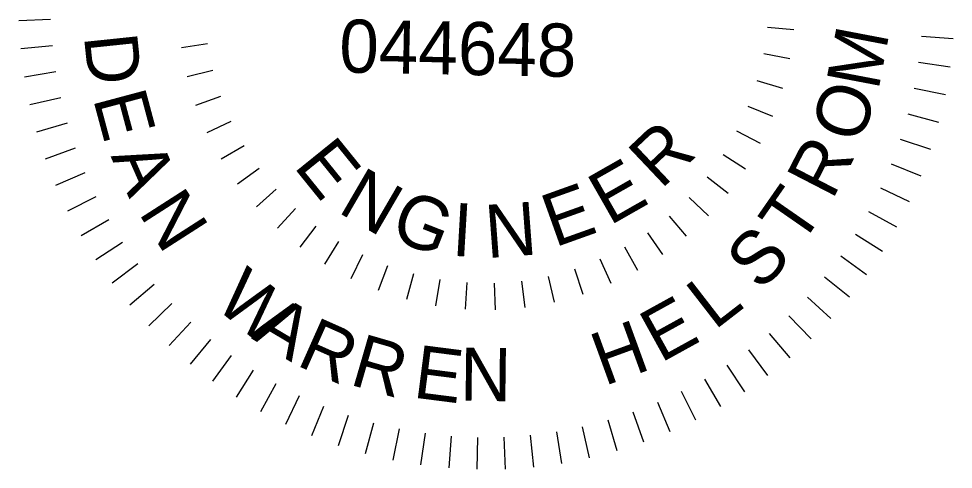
# Model space of a CAD drawing. Extents: x 0 to 4772457, y -312190 to 1506.
# Drawn here: x 3.6903 to 3.8118, y 1.3954 to 1.454 of the extents above; entities that cross this region are included whole.
import ezdxf

# ---------------------------------------------------------------- set-up
doc = ezdxf.new("R2010")
doc.units = 0
doc.layers.add('Phasing Diagram CELL', color=7, linetype='Continuous')

msp = doc.modelspace()

# ---------------------------------------------------------------- linework, layer by layer
at = {"layer": 'Phasing Diagram CELL'}
for p, q in [((3.6903447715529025, 1.4537591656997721), (3.6944888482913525, 1.4539254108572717)), ((3.7911069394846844, 1.452534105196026), (3.787667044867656, 1.4528508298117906)), ((3.7114942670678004, 1.450262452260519), (3.714908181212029, 1.4507772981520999)), ((3.8118311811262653, 1.451351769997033), (3.8076969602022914, 1.4516822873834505)), ((3.690606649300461, 1.4500932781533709), (3.6947298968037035, 1.4505087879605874)), ((3.787188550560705, 1.4494652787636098), (3.7905882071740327, 1.44882345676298)), ((3.811424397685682, 1.4476989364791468), (3.807320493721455, 1.448277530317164)), ((3.6910828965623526, 1.446448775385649), (3.695176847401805, 1.447113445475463)), ((3.7122503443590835, 1.4464578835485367), (3.7156017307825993, 1.4473003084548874)), ((3.7896535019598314, 1.4449241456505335), (3.7863377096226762, 1.4458985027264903)), ((3.8108040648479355, 1.4440764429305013), (3.8067396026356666, 1.444902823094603)), ((3.69178348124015, 1.442842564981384), (3.6958304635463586, 1.443748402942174)), ((3.7133774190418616, 1.44274915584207), (3.7166323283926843, 1.4439105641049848)), ((3.788380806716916, 1.4412629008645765), (3.78517456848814, 1.442552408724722)), ((3.809961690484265, 1.4405008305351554), (3.8059533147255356, 1.4415660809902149)), ((3.692698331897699, 1.4392751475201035), (3.6966905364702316, 1.4404305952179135)), ((3.7148582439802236, 1.4391704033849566), (3.71798235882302, 1.4406427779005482)), ((3.7867591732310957, 1.4377457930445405), (3.7836958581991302, 1.439340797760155)), ((3.716667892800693, 1.4357480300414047), (3.7196432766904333, 1.4375065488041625)), ((3.808905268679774, 1.4369723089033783), (3.80496210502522, 1.438285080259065)), ((3.6938293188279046, 1.4357806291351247), (3.697740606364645, 1.4371775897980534)), ((3.784815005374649, 1.4343977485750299), (3.7819120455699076, 1.436272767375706)), ((3.8076367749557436, 1.4335254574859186), (3.8037843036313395, 1.4350763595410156)), ((3.695176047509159, 1.4323583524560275), (3.6989889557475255, 1.4339808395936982)), ((3.7188069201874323, 1.4325079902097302), (3.7215991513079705, 1.4345531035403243)), ((3.782549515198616, 1.431244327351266), (3.7798405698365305, 1.4333988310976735)), ((3.721250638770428, 1.4295012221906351), (3.7238255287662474, 1.4317997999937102)), ((3.8061558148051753, 1.4301596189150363), (3.802409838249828, 1.4319314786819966)), ((3.6967131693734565, 1.4290194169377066), (3.700427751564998, 1.430874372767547)), ((3.77998826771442, 1.42833796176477), (3.777507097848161, 1.4307361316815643)), ((3.7239649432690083, 1.426738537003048), (3.7263132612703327, 1.4292814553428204)), ((3.804487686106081, 1.4268835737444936), (3.8008495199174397, 1.4288845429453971)), ((3.6984578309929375, 1.4257783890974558), (3.7020483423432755, 1.427858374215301)), ((3.777166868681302, 1.425684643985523), (3.7749211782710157, 1.4283175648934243)), ((3.72694218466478, 1.4242536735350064), (3.7290285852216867, 1.4270070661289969)), ((3.774093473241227, 1.4233188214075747), (3.7721178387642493, 1.4261532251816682)), ((3.802616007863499, 1.423714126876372), (3.799110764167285, 1.4259353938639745)), ((3.700393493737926, 1.4226535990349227), (3.703851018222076, 1.4249419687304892)), ((3.7301398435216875, 1.4220642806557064), (3.7319554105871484, 1.4250115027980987)), ((3.7708117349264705, 1.4212581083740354), (3.769114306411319, 1.4242747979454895)), ((3.7335405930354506, 1.4201963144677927), (3.7350593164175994, 1.423304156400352)), ((3.767339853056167, 1.4195262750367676), (3.765945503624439, 1.422691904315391)), ((3.800558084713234, 1.4206687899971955), (3.7971935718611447, 1.4230929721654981)), ((3.7025114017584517, 1.4196536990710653), (3.705827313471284, 1.4221429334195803)), ((3.73710193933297, 1.4186597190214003), (3.7383152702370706, 1.4219020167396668)), ((3.76371977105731, 1.418132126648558), (3.7626360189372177, 1.4214201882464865)), ((3.7416631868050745, 1.4208241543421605), (3.7407650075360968, 1.4174812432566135)), ((3.7599874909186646, 1.4171001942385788), (3.759223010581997, 1.420475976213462)), ((3.7983223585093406, 1.4177553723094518), (3.795108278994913, 1.4203736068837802)), ((3.7048126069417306, 1.416778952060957), (3.707969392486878, 1.4194684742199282)), ((3.744581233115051, 1.4166598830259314), (3.745145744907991, 1.4200692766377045)), ((3.748430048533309, 1.416206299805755), (3.748660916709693, 1.4196565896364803)), ((3.752303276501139, 1.4161295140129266), (3.752209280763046, 1.4195864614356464)), ((3.7561675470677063, 1.4164302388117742), (3.7557382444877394, 1.4198591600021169)), ((3.7959100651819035, 1.4149738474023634), (3.7928621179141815, 1.417786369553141)), ((3.7072785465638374, 1.4140553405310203), (3.7102679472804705, 1.4169281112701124)), ((3.7933373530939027, 1.4123499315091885), (3.790464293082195, 1.4153391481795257)), ((3.709902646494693, 1.4114823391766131), (3.7127150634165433, 1.414529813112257)), ((3.790614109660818, 1.4098834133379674), (3.78792411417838, 1.4130403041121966)), ((3.712684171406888, 1.4090700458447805), (3.715302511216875, 1.4122845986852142)), ((3.7877389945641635, 1.4075827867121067), (3.7852494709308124, 1.410898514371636)), ((3.7155976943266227, 1.4068347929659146), (3.71802177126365, 1.4101988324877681)), ((3.7186427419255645, 1.4047766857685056), (3.720864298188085, 1.408282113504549)), ((3.7847388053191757, 1.4054646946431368), (3.782450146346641, 1.4089220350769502)), ((3.781614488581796, 1.4035289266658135), (3.7795337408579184, 1.4071193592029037)), ((3.721812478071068, 1.4029051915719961), (3.723813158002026, 1.406543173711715)), ((3.725088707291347, 1.4012367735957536), (3.726860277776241, 1.404982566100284)), ((3.778373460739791, 1.4017842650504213), (3.776518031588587, 1.4054989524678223)), ((3.7284542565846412, 1.3997556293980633), (3.730005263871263, 1.4036085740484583)), ((3.775033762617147, 1.4002470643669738), (3.77341203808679, 1.4040600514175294)), ((3.731901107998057, 1.398487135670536), (3.7332141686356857, 1.4024304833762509)), ((3.7716117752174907, 1.3989005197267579), (3.7702148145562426, 1.4028118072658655)), ((3.7354297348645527, 1.3974311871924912), (3.7364946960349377, 1.401439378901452)), ((3.764550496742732, 1.3968542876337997), (3.763644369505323, 1.4009010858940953)), ((3.768117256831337, 1.3977695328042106), (3.76696180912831, 1.4017617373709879)), ((3.739005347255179, 1.3965888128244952), (3.739831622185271, 1.400652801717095)), ((3.742628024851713, 1.3959681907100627), (3.743206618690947, 1.4000720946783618)), ((3.7462806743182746, 1.3955616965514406), (3.7466116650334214, 1.3996958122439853)), ((3.7499549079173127, 1.3953774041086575), (3.750036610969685, 1.39952521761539)), ((3.7536332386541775, 1.3954159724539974), (3.753466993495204, 1.3995600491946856)), ((3.757299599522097, 1.3956777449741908), (3.756883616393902, 1.3998010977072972)), ((3.760943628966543, 1.3961540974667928), (3.7602789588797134, 1.40024804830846))]:
    msp.add_line(p, q, dxfattribs=at)

# ---------------------------------------------------------------- texts
for s, height, rotation, p in [('044648', 0.006908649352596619, 358.86477097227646, (3.731960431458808, 1.447010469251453)), ('M', 0.006908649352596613, 79.17730440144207, (3.8020815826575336, 1.444537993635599)), ('D', 0.006908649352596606, 275.9810543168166, (3.698815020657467, 1.4517308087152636)), ('E', 0.006908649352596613, 284.9836162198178, (3.699977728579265, 1.4436279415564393)), ('O', 0.0069086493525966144, 71.18290524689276, (3.7997045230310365, 1.437507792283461)), ('R', 0.006908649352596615, 43.42965986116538, (3.7738222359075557, 1.4317003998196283)), ('E', 0.006908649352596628, 308.9348626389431, (3.7259673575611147, 1.4347835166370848)), ('R', 0.006908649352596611, 62.73365891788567, (3.796093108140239, 1.4302845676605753)), ('A', 0.0069086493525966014, 293.8062332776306, (3.7022720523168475, 1.4361093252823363)), ('E', 0.00690864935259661, 29.658573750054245, (3.767145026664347, 1.4270149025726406)), ('N', 0.006908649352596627, 329.7899348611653, (3.731655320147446, 1.4289099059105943)), ('E', 0.006908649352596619, 19.67269319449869, (3.759999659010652, 1.42420726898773)), ('T', 0.00690864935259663, 55.2280020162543, (3.791919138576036, 1.4241985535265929)), ('N', 0.006908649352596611, 302.6888628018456, (3.705833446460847, 1.4287685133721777)), ('G', 0.006908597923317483, 338.5561681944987, (3.73835290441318, 1.4255365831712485)), ('I', 0.0069086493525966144, 356.6509654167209, (3.746536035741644, 1.4231624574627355)), ('N', 0.0069086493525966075, 4.280626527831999, (3.7512192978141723, 1.4228382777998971)), ('S', 0.006908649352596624, 46.55524668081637, (3.7867780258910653, 1.4183959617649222)), ('W', 0.006908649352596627, 320.3641031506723, (3.7155901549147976, 1.416666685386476)), ('L', 0.006908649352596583, 37.76263585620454, (3.780786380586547, 1.4133927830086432)), ('E', 0.0069086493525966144, 28.880006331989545, (3.7737793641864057, 1.4091618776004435)), ('A', 0.006908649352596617, 329.31254993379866, (3.720542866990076, 1.412407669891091)), ('R', 0.006908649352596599, 336.0278679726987, (3.7262652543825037, 1.408980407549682)), ('H', 0.006908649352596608, 19.997376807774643, (3.766449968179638, 1.4061758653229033)), ('R', 0.006908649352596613, 343.8076622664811, (3.733189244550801, 1.406451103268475)), ('E', 0.006908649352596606, 352.71575389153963, (3.7414787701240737, 1.404733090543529)), ('N', 0.006908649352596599, 359.3001307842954, (3.7476769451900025, 1.4043037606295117))]:
    msp.add_text(s, height=height, rotation=rotation, dxfattribs=at).set_placement(p)

doc.saveas('drawing.dxf')
